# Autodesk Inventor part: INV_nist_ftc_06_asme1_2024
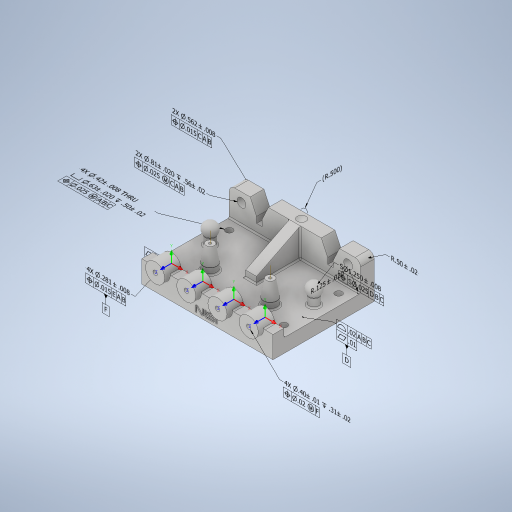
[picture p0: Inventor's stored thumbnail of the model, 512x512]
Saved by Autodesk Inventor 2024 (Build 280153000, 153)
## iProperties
Created: 2016-11
Part Number: INV_nist_ftc_06_asme1_2024
Material: Generic
Document SubType Name: Modeling
Designer: t_liuje
Density: 1 g/cm^3
Appearance: Default
Author: t_liuje
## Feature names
1. Extrusion1
2. Extrusion2
3. Extrusion3
4. Revolution1
5. Rectangular Pattern1
6. Loft1
7. Extrusion4
8. Hole8
9. Extrusion8
10. Extrusion7
11. Hole4
12. Fillet2
13. Revolution2
14. Extrusion5
15. Hole6
16. Mirror2
17. Fillet4
18. Hole9
19. Rectangular Pattern2
20. Hole10
21. Hole11
22. Hole12
23. Extrusion9
## Parameters: d0 = 31.75 mm, d1 = 31.75 mm, d2 = 25.4 mm, d3 = 234.95 mm, d4 = 50.8 mm, d5 = 97.79 mm, d6 = 304.8 mm, d7 = 0, d9 = 15.24 mm, d10 = 2.54 mm, d11 = 25.4 mm, d12 = 0, d13 = 0, d14 = 2.54 mm, d15 = 2.54 mm, d16 = 115 deg, d17 = 115 deg, d18 = 63.5 mm, d19 = 13.97 mm, d20 = 12.7 mm, d21 = 31.75 mm, d22 = 25.4 mm, d23 = 0, d25 = 31.75 mm, d28 = 82.55 mm, d29 = 76.2 mm, d30 = 15.24 mm, d31 = 0, d35 = -31.75 mm, d39 = 96.52 mm, d40 = 11.43 mm, d41 = 31.75 mm, d42 = 31.75 mm, d43 = 90 deg, d44 = 38.1 mm, d45 = 19.05 mm, d46 = 0, d47 = 90 deg, d48 = 0, d49 = 90 deg, d50 = 44.45 mm, d51 = 44.45 mm, d52 = 50.8 mm, d53 = 50.8 mm, d54 = 43.815 mm, d55 = 72.39 mm, d56 = 38.1 mm, d57 = 0, d58 = 25.4 mm, d59 = 25.4 mm, d76 = 21.59 mm, d77 = 28.575 mm, d85 = 25.4 mm, d86 = 57.15 mm, d87 = 10.541 mm, d88 = 19.05 mm, d89 = 15.875 mm, d90 = 12.7 mm, d91 = 82 deg, d92 = 31.75 mm, d93 = 0, d104 = 12.7 mm, d106 = 25.4 mm, d109 = 90 deg, d269 = 6.35 mm, d270 = 124.46 mm, d271 = 2.54 mm, d272 = 0, d436 = 25.4 mm, d437 = 25.4 mm, d413 = 6.35 mm, d414 = 19.05 mm, d415 = 9.525 mm, d416 = 6.35 mm, d417 = 82 deg, d418 = 12.7 mm, d419 = 118 deg, d477 = -19.05 mm, d532 = 152.4 mm, d533 = 38.1 mm, d534 = 0, d535 = 90 deg, d536 = 0, d537 = 180 deg, d543 = 0, d544 = 0, d545 = 0, d546 = 90 deg, d547 = 0, d548 = 180 deg, d570 = 0, d571 = 0, d572 = 0, d573 = 90 deg, d574 = 0, d575 = 180 deg, d813 = 241.3 mm, d814 = 20.6248 mm, d815 = 19.05 mm, d816 = 9.525 mm, d817 = 6.35 mm, d818 = 82 deg, d819 = 14.224 mm, d820 = 0, d821 = 0, d822 = 0, d824 = 3.175 mm, d825 = 10.16 mm, d826 = 19.05 mm, d827 = 9.525 mm, d828 = 6.35 mm, d829 = 82 deg, d830 = 7.874 mm, d831 = 0, d832 = 10.16 mm, d833 = 19.05 mm, d834 = 9.525 mm, d835 = 6.35 mm, d836 = 82 deg, d837 = 7.874 mm, d838 = 0, d839 = 10.16 mm, d840 = 19.05 mm, d841 = 9.525 mm, d842 = 6.35 mm, d843 = 82 deg, d844 = 7.874 mm, d845 = 0, d846 = 10.16 mm, d847 = 19.05 mm, d848 = 9.525 mm, d849 = 6.35 mm, d850 = 82 deg, d851 = 7.874 mm, d852 = 0, d1030 = -15.24 mm, d1042 = 0, d1202 = 72.39 mm, d1286 = 0, d1287 = 0, d1288 = 0, d1289 = 90 deg, d1290 = 0, d1291 = -180 deg, d1292 = 0, d1293 = 0, d1294 = 0, d1295 = 90 deg, d1296 = 0, d1297 = 90 deg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
